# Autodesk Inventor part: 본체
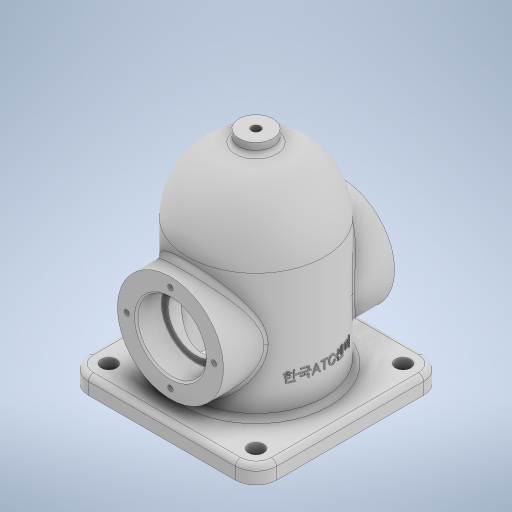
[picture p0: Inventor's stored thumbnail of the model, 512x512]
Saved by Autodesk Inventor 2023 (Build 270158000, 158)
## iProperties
Created: 2025-04
Part Number: 본체
Material: 일반
Document SubType Name: Modeling
Designer: ADMIN_PC
Density: 1 g/cm^3
Appearance: 기본값
Author: ADMIN_PC
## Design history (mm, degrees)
node "작업 평면1"
sketch "스케치1"
  geometry: L1 (-55, 55)-(55, 55); L2 (55, 55)-(55, -55); L3 (55, -55)-(-55, -55); L4 (-55, -55)-(-55, 55); L5 (-55, 55)-(55, -55); L6 (55, 55)-(-55, -55); 1 further point
  constraints: 12 end point, 2 midpoint, 2 parallel, 1 horizontal, 1 perpendicular
  dimensions: "d1" = 110 distance of L2.end L3.end; "d2" = 110 distance of L1.end L2.end
extrude "돌출1" new body sketch "스케치1" distance "d3" = 10; taper "d4" = 0 deg
sketch "스케치2"
  geometry: C1 r 40 at (0, 0); 1 further point
  constraints: 1 centre point, 1 coincident
  dimensions: "d5" = 80 diameter of C1
extrude "돌출2" join sketch "스케치2" distance "d6" = 74; taper "d7" = 0 deg
sketch "스케치3"
  geometry: L1 (36, -40)-(36, 40) reference; L2 (76, 0)-(36, 0); L3 (-74.457, 0)-(110.741, 0) reference; A1 r 40 centre (36, 0) between (76, 0) and (36, 40); 1 further point
  constraints: 2 end point, 2 point on circle, 1 centre point, 1 horizontal, 1 midpoint
revolve "회전1" sketch "스케치3" stored, may be unused: angle "d8" = 90 deg
sketch "스케치4"
  geometry: C1 r 10 at (0, 0); 1 further point
  constraints: 1 centre point, 1 coincident
  dimensions: "d9" = 20 diameter of C1
extrude "돌출3" join sketch "스케치4" distance "d10" = 129; taper "d11" = 0 deg
sketch "스케치5"
  geometry: L1 (36, -40)-(36, 40) reference; L2 (-73.8, 0)-(106.8, 0) reference; L3 (36, 32)-(-48, 32); L4 (-48, -55)-(-48, 55) reference; L5 (-48, 32)-(-48, 0); L6 (68, 0)-(-48, 0); A1 r 32 centre (36, 0) between (68, 0) and (36, 32); 2 further points
  constraints: 6 end point, 4 point on line, 2 midpoint, 2 point on circle, 1 centre point, 1 horizontal, 1 perpendicular
  dimensions: "d12" = 32 radius of A1
sketch "스케치6"
  geometry: L1 (55, -48)-(-55, -48) reference; L2 (0, -48)-(0, 0); C1 r 31 at (0, 0)
  constraints: 2 end point, 1 centre point, 1 coincident, 1 midpoint, 1 vertical
  dimensions: "d13" = 48 distance of L2.start L2.end (derived); "d14" = 62 diameter of C1
extrude "돌출4" join sketch "스케치6" stored distance "d15" = 100; taper "d16" = 0 deg
revolve "회전2" stored, may be unused: angle "d17" = 90 deg
sketch "스케치7"
  geometry: C1 r 16.5 at (0, 0); 1 further point
  constraints: 1 centre point, 1 coincident
  dimensions: "d18" = 33 diameter of C1
extrude "돌출5" cut sketch "스케치7" extent not by distance; stored distance "d19" = 0; taper "d20" = 0 deg
sketch "스케치8"
  geometry: C1 r 16.5 at (0, 0) reference; C2 r 20 at (0, 0); 1 further point
  constraints: 1 centre point, 1 coincident
  dimensions: "d21" = 40 diameter of C2
extrude "돌출6" cut sketch "스케치8" distance "d22" = 15; taper "d23" = 0 deg
sketch "스케치9" dims "d24" = 51
  geometry: L1 (0, -73.8)-(0, 106.8) reference; 3 further points
  constraints: 1 coincident, 1 point on line, 1 vertical alignment, 2 other
hole "구멍1" sketch "스케치9" at (0, 25.5) diameter "d25" = 3.242; stored, may be unused: countersink angle "d29" = 90 deg, drill point angle "d31" = 118 deg; dims "d26" = 8, "d27" = 4, "d28" = 2, "d30" = 10
sketch "스케치10"
  geometry: 2 further points
  constraints: 1 coincident
hole "구멍2" sketch "스케치10" at (0, 0) diameter "d35" = 5.1881; stored, may be unused: countersink angle "d39" = 90 deg, drill point angle "d41" = 118 deg; dims "d36" = 20, "d37" = 4, "d38" = 2, "d40" = 21
fillet "모깎기1" dims "d42" = 12
sketch "스케치11"
  geometry: C1 r 4.5 at (-43, -43); C2 r 4.5 at (-43, 43); C3 r 4.5 at (43, -43); C4 r 4.5 at (43, 43); A1 r 12 centre (-43, -43) between (-55, -43) and (-43, -55) reference; A2 r 12 centre (-43, 43) between (-43, 55) and (-55, 43) reference; A3 r 12 centre (43, -43) between (43, -55) and (55, -43) reference; A4 r 12 centre (43, 43) between (55, 43) and (43, 55) reference; 1 further point
  constraints: 4 centre point, 4 coincident
  dimensions: "d43" = 9 diameter of C1; "d44" = 9 diameter of C2; "d45" = 9 diameter of C3; "d46" = 9 diameter of C4
extrude "돌출7" cut sketch "스케치11" extent not by distance; stored distance "d47" = 0; taper "d48" = 0 deg
node "작업 평면2"
sketch "스케치12"
  geometry: L1 (-48, -43)-(-48, 43) reference; L2 (-48, 0)-(-18, 0); 2 further points
  constraints: 2 end point, 1 coincident, 1 horizontal, 1 midpoint, 1 other
  dimensions: "d50" = 30 distance of L2.start L2.end
feature "엠보싱1" sketch "스케치12" dims "d1" = 110, "d2" = 110, "d9" = 20, "d51" = 0.5, "d52" = 0
fillet "모깎기2" dims "d53" = 0.3
fillet "모깎기3" dims "d54" = 3
chamfer "모따기1" distance "d55" = 1; stored, may be unused: second distance "d56" = 2, angle "d57" = 45 deg
feature "̥耀̧耀̩耀̫耀̭耀̯耀̱耀̳耀" dims "d0" = -48, "d1" = 110, "d2" = 110, "d3" = 10, "d4" = 0, "d5" = 80, "d6" = 74, "d7" = 0, "d8" = 90 deg, "d9" = 20, "d10" = 129, "d11" = 0, "d12" = 32, "d13" = 48 (derived), "d14" = 62, "d15" = 100, "d16" = 0, "d17" = 90 deg, "d18" = 33, "d19" = 0, "d20" = 0, "d21" = 40, "d22" = 15, "d23" = 0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
node "솔리드1"
mirror "미러1"
pattern_circular "원형 패턴1" dims angle "d33" = 360 deg
mirror "미러2"
feature "A9D066F2-1C7D-4E18-AEED-F7BC21143FA4" dims "d25" = 3.242, "d26" = 8, "d27" = 4, "d28" = 2, "d29" = 90 deg, "d30" = 10, "d31" = 118 deg
